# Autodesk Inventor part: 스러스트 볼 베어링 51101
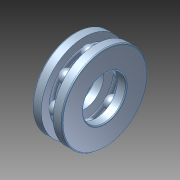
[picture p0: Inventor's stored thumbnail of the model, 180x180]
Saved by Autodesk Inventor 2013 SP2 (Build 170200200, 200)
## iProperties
Created: 2024-07
Part Number: 스러스트 볼 베어링 51101
Material: Generic
Document SubType Name: Modeling
Designer: 601
Density: 1 g/cm^3
Author: 601
변환 표준: STEP AP214IS
전처리기: Build: 200, Release: 2013 SP2 Update 6 - Date: Thu 07/17/2014
전송 단위: 밀리미터
불확실성: 0.01
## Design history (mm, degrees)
node "스러스트 볼 베어링 511011"
body "Solid1"
node "Solid1_1"
node "Solid1_2"
node "Solid1_3"
node "Solid1_4"
node "Solid1_5"
node "Solid1_6"
node "Solid1_7"
node "Solid1_8"
node "Solid1_9"
node "기준1"
node "기준2"
node "기준3"
node "기준4"
node "기준5"
node "기준6"
node "기준7"
node "기준8"
node "기준9"
node "기준10"
